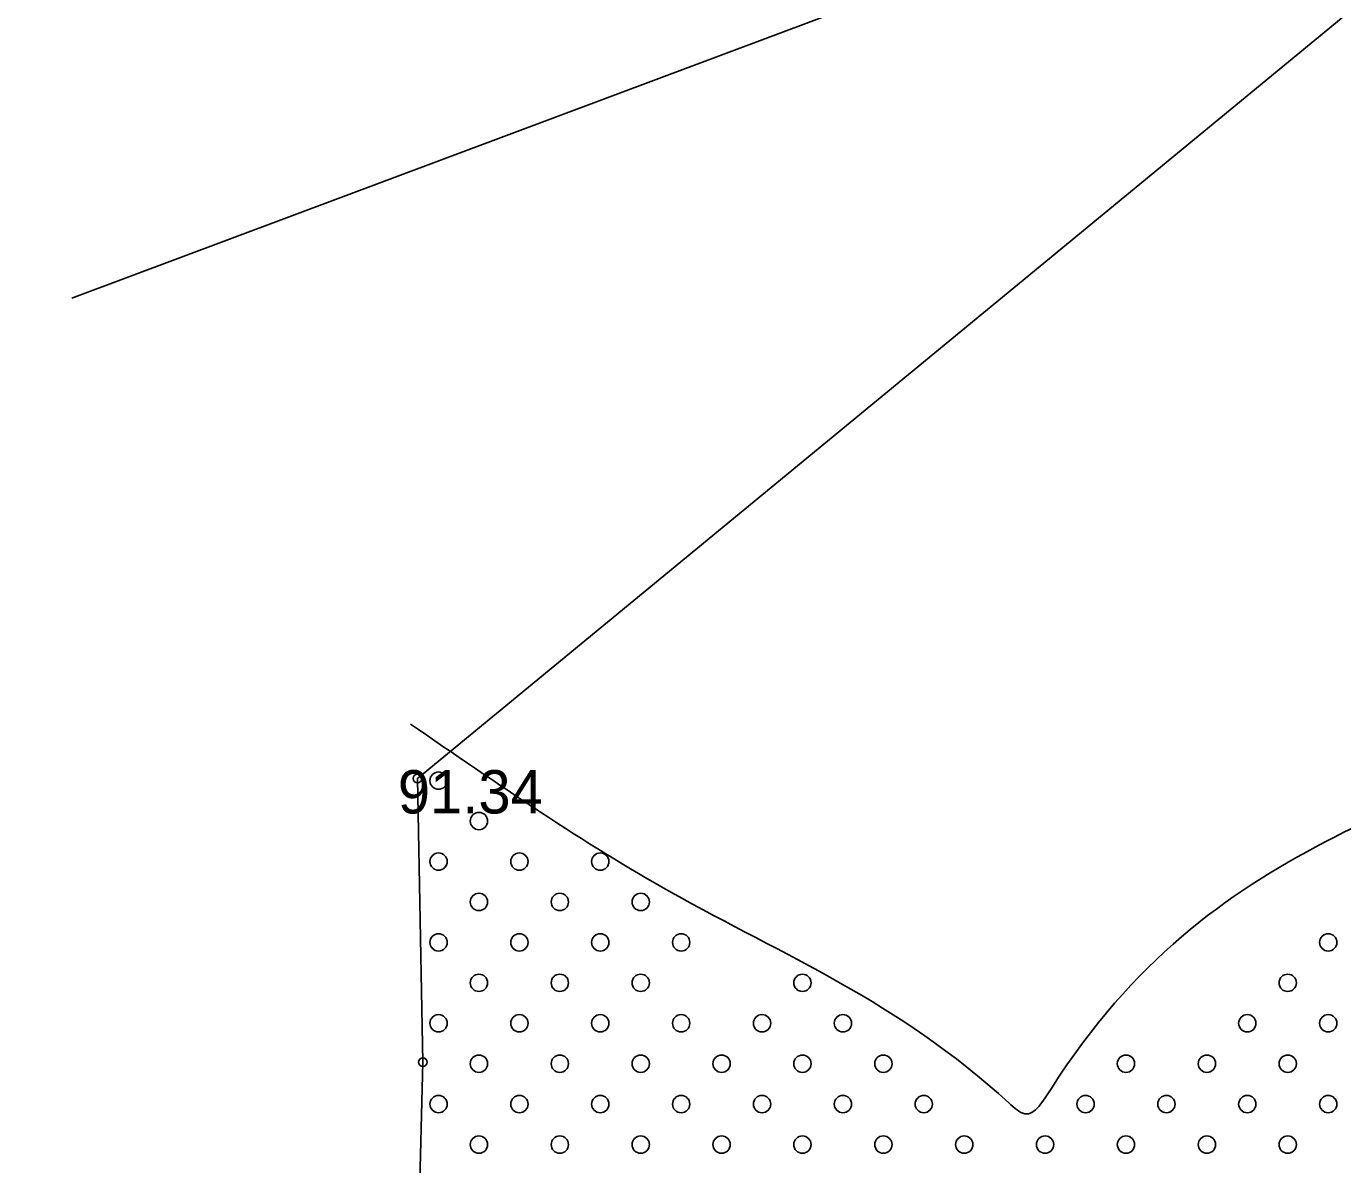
# Model space of a CAD drawing. Extents: x 316000 to 728450, y 314368 to 726000.
# Drawn here: x 725524.8 to 725638.8, y 315558.3 to 315656.8 of the extents above; entities that cross this region are included whole.
import ezdxf

# ---------------------------------------------------------------- set-up
doc = ezdxf.new("R2010")
doc.units = 0
for name, color, linetype in [('24', 7, 'Continuous'), ('HIDG_GRAV_####_####_#', 7, 'Continuous'), ('RAMI_UZMR_####_####_#', 7, 'Continuous'), ('RELJ_AATZ_####_TKST_#', 7, 'Continuous'), ('RELJ_ELEM_####_####_#', 7, 'Continuous'), ('RELJ_NOGA_####_####_#', 7, 'Continuous'), ('TERT_ELEM_####_####_#', 7, 'Continuous'), ('TERT_KONT_####_####_#', 7, 'Continuous')]:
    doc.layers.add(name, color=color, linetype=linetype)

msp = doc.modelspace()

# ---------------------------------------------------------------- linework, layer by layer
at = {"layer": '24'}
msp.add_line((725891.35, 315769.28), (725528.77, 315633.25), dxfattribs=at)
at = {"layer": 'HIDG_GRAV_####_####_#'}
for points in [[(725743.94, 315631.87), (725731.18, 315638.51), (725730.06, 315638.49), (725729.04, 315637.53), (725728.07, 315636.19), (725727.1, 315635.02), (725611.68, 315529.82)], [(725741.16, 315628.11), (725732.01, 315633.48), (725729.37, 315630.94), (725612.67, 315527.51), (725555.21, 315474.31)]]:
    msp.add_spline(points, degree=3, dxfattribs=at)
at = {"layer": 'RAMI_UZMR_####_####_#'}
msp.add_lwpolyline([(727254.69, 315085.95), (727002.7, 315002.84), (726508.21, 314868.03), (726416.7, 314837.05), (725982.38, 314530.96), (725916.44, 314513.26), (725799.16, 314549.2), (725735.9, 314623.63), (725701.82, 314711.1), (725697.25, 315112.64), (725659.91, 315163.35), (725614.81, 315211.65), (725561.8, 315231.45), (725500.09, 315274.21), (725474.77, 315308.26), (725484.26, 315374.77), (725505.03, 315405.04), (725554.87, 315404.25), (725559.14, 315567.14), (725558.67, 315591.68), (725662, 315676.73), (726089.69, 315915.19)], dxfattribs=at)
at = {"layer": 'RELJ_ELEM_####_####_#'}
for centre in [(725558.67, 315591.68), (725559.14, 315567.14)]:
    msp.add_circle(centre, 0.375, dxfattribs=at)
at = {"layer": 'RELJ_NOGA_####_####_#'}
for points in [[(725744.7, 315632.91), (725731.21, 315640.04), (725729.06, 315639.58), (725728.31, 315638.8), (725727.7, 315637.94), (725727.11, 315637.1), (725726.42, 315636.33), (725610.41, 315531.97)], [(725740.86, 315626.98), (725732.5, 315631.14), (725731.68, 315631.15), (725730.9, 315630.55), (725730.16, 315629.69), (725729.45, 315628.9), (725615, 315525.02)]]:
    msp.add_spline(points, degree=3, dxfattribs=at)
at = {"layer": 'TERT_ELEM_####_####_#'}
for centre in [(725560.5, 315591.5), (725564, 315588), (725560.5, 315584.5), (725567.5, 315584.5), (725574.5, 315584.5), (725564, 315581), (725571, 315581), (725578, 315581), (725560.5, 315577.5), (725567.5, 315577.5), (725574.5, 315577.5), (725581.5, 315577.5), (725637.5, 315577.5), (725564, 315574), (725571, 315574), (725578, 315574), (725592, 315574), (725634, 315574), (725560.5, 315570.5), (725567.5, 315570.5), (725574.5, 315570.5), (725581.5, 315570.5), (725588.5, 315570.5), (725595.5, 315570.5), (725630.5, 315570.5), (725637.5, 315570.5), (725564, 315567), (725571, 315567), (725578, 315567), (725585, 315567), (725592, 315567), (725599, 315567), (725620, 315567), (725627, 315567), (725634, 315567), (725560.5, 315563.5), (725567.5, 315563.5), (725574.5, 315563.5), (725581.5, 315563.5), (725588.5, 315563.5), (725595.5, 315563.5), (725602.5, 315563.5), (725616.5, 315563.5), (725623.5, 315563.5), (725630.5, 315563.5), (725637.5, 315563.5), (725564, 315560), (725571, 315560), (725578, 315560), (725585, 315560), (725592, 315560), (725599, 315560), (725606, 315560), (725613, 315560), (725620, 315560), (725627, 315560), (725634, 315560)]:
    msp.add_circle(centre, 0.75, dxfattribs=at)
at = {"layer": 'TERT_KONT_####_####_#'}
msp.add_spline([(725558.07, 315596.4), (725580.66, 315581.82), (725609.87, 315563.6), (725611.24, 315562.66), (725613.57, 315564.91), (725663.65, 315599.1), (725664.61, 315599.65), (725676.57, 315588.96)], degree=3, dxfattribs=at)

# ---------------------------------------------------------------- texts
at = {"layer": 'RELJ_AATZ_####_TKST_#'}
msp.add_text('91.34', height=3.75, dxfattribs=at).set_placement((725556.98, 315588.66))

doc.saveas('drawing.dxf')
